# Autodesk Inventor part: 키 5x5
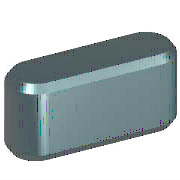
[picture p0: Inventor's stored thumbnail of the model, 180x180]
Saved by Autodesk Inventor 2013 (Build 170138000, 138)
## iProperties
IsCustomPart: 1
Created: 2012-02
Part Number: 키 5x5
Material: 강철, 연강
Description: 키 및 해당 키홈
Document SubType Name: Modeling
Standard: KS B 1311
Designer: mduedu
Standards Organization: KS
Language: ko-KR
Size Designation: 5 x 5 x 16
Categories: <MemberInstance><Categories><Category DisplayName="샤프트 부품" InternalName="7f7aeb1f-a693-4053-b835-cee3144e0d98" Mnemonic="SHFT"><Category DisplayName="키" Interna
Density: 1 g/cm^3
Author: mduedu
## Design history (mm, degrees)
workplane "Work Plane1"
workplane "Work Plane2"
sketch "스케치1"
  geometry: L1 (2.5, 2.5)-(13.5, 2.5); L2 (13.5, -2.5)-(2.5, -2.5); L3 (0, 9.4)-(0, -7.4) reference; L4 (-5, 0)-(30, 0) reference; L5 (16, 0)-(16, 7); A1 r 2.5 centre (2.5, 0) between (2.5, 2.5) and (2.5, -2.5); A2 r 2.5 centre (13.5, 0) between (13.5, -2.5) and (13.5, 2.5)
  constraints: 6 end point, 5 point on circle, 4 tangent, 3 point on line, 2 centre point, 1 horizontal, 1 parallel, 1 perpendicular
  dimensions: "d0" = 2.5 radius of A1 (= 0.5 x PB); "d13" = 2.5 radius of A2 (= 0.5 x PB); "d14" = 16 distance between parallel lines of L5 L3 (= NLG)
extrude "본체1" new body sketch "스케치1" taper "d3" = 0 deg; stored distance "d4" = 10
workplane "Work Plane3"
body "Solid1"
chamfer "모따기1" distance "d8" = 0.4 (= PHH); stored, may be unused: second distance "d9" = 0.4 (= PHH), angle "d15" = 45 deg
other parameters: "d1" = -3 (= -PNT), "d2" = 2 (= PH - PNT), "NLG" = 16 [user parameter; used in 3 equation terms], "PB" = 5 [user parameter; used in 2 equation terms], "PNT" = 3 [user parameter; used in 2 equation terms], "PH" = 5 [user parameter; used in 1 equation term], "PHH" = 0.4 [user parameter; used in 2 equation terms], "d10" = 0, "d16" = 0, "d17" = 0, "d18" = 0, "WDMIN" = 12 [user parameter], "PLB2" = 16 (= NLG) [user parameter], "WDMAX" = 17 [user parameter], "PLB1" = 16 (= NLG) [user parameter], "RR" = 0.16 [user parameter], "PUEB" = 2.3 [user parameter]
